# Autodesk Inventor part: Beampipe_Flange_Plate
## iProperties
Shininess: 64.0
Length Units: 11269
Angle Units: 11279
Time Units: 11290
Mass Units: 11283
Length Display Precision: 3
Angle Display Precision: 2
Compacted: True
Part Number: Beampipe_Flange_Plate
Document SubType Name: Modeling
Created: 2004-08
Designer: John Blackburn
Manufacturer: Standard
Standards Organization: Custom
Density: 0.0
Volumn: 0.0
Area: 0.0
PropertySet Name: Model Information
Control State: 0
Master: False
Checked Out: False
Author: John Blackburn
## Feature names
1. Extrusion1
